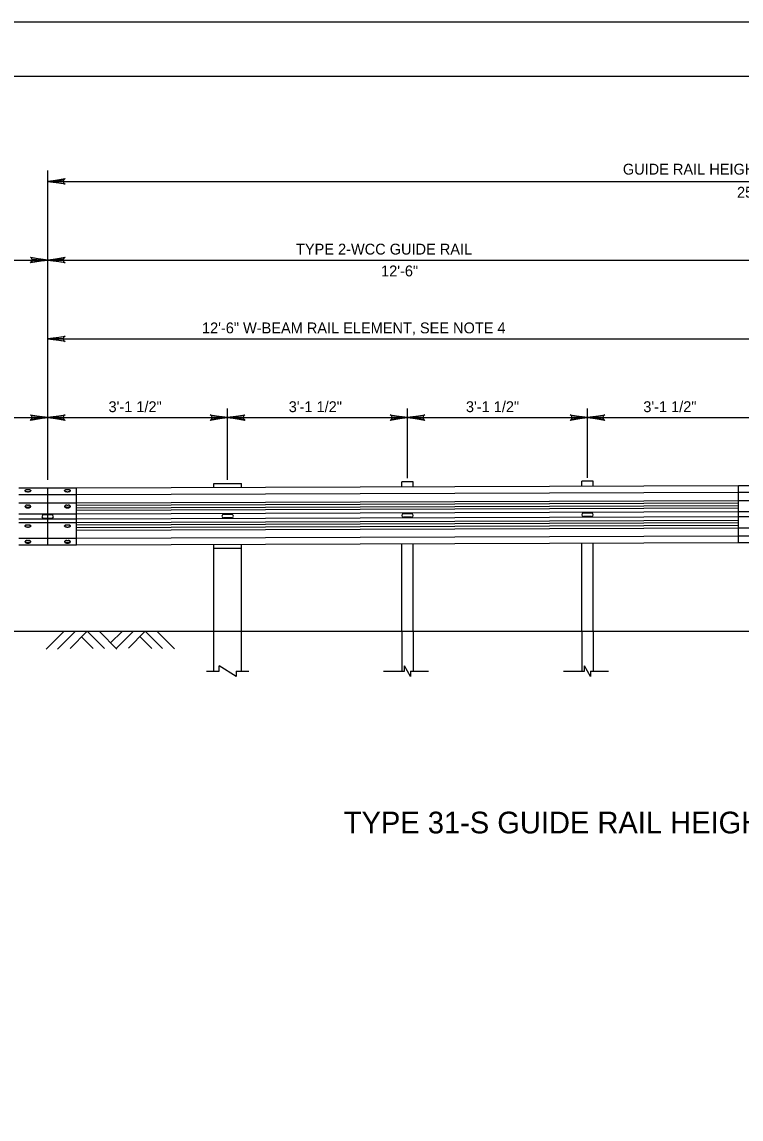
# Model space of a CAD drawing. Extents: x 637628 to 640188, y 298266 to 300751.
# Drawn here: x 639280.6 to 639479, y 299150.6 to 299453.6 of the extents above; entities that cross this region are included whole.
import ezdxf

# ---------------------------------------------------------------- set-up
doc = ezdxf.new("R2010")
doc.units = 0
for name, color, linetype in [('1', 7, 'Continuous'), ('2', 7, 'Continuous'), ('PLT-BNDY', 7, 'Continuous'), ('S-ABUT-CONC', 7, 'Continuous'), ('S-ANNO-CELL', 7, 'Continuous'), ('S-ANNO-T120-01', 7, 'Continuous')]:
    doc.layers.add(name, color=color, linetype=linetype)

msp = doc.modelspace()

# ---------------------------------------------------------------- linework, layer by layer
at = {"layer": '1'}
for p, q in [((639295.62, 299309.11), (639295.62, 299324.84)), ((639478.35, 299309.75), (639478.35, 299325.48))]:
    msp.add_line(p, q, dxfattribs=at)
msp.add_lwpolyline([(639945.52, 298874.58), (639945.52, 299438.55), (639159.55, 299438.55), (639159.55, 298874.58), (639945.52, 298874.58), (639945.52, 298900.93), (639745.53, 298900.93), (639745.53, 298965.61), (639945.52, 298965.61), (639945.52, 298994.57), (639745.53, 298994.57), (639745.53, 298874.58), (639824.33, 298874.58), (639824.33, 298900.93), (639824.33, 298874.58), (639901.33, 298874.58), (639901.33, 298900.93), (639901.33, 298888.62), (639945.52, 298888.62)], dxfattribs=at)
at = {"layer": '2'}
for p, q in [((639333.5, 299326.12), (639341.14, 299326.12)), ((639295.69, 299315.26), (639295.62, 299315.28)), ((639333.5, 299308.27), (639341.14, 299308.27)), ((639292.05, 299285.2), (639287.28, 299280.42)), ((639295.16, 299285.2), (639290.39, 299280.42)), ((639298.57, 299285.33), (639293.84, 299280.6)), ((639300.23, 299280.56), (639297.01, 299283.77)), ((639303.34, 299280.56), (639298.57, 299285.33)), ((639306.75, 299280.42), (639302.02, 299285.15)), ((639308.18, 299285.29), (639305.03, 299282.14)), ((639311.28, 299285.29), (639306.51, 299280.52)), ((639314.6, 299285.33), (639309.96, 299280.69)), ((639316.36, 299280.57), (639313.14, 299283.78)), ((639319.37, 299280.56), (639314.6, 299285.33)), ((639322.62, 299280.52), (639317.81, 299285.33)), ((639333.5, 299285.33), (639341.14, 299285.33))]:
    msp.add_line(p, q, dxfattribs=at)
for points in [[(639292.2, 299408.98), (639292.03, 299409.31), (639287.66, 299409.55), (639292.2, 299408.98), (639292.44, 299408.78), (639287.66, 299409.55), (639292.03, 299409.76), (639292.19, 299410.09), (639287.66, 299409.55), (639292.44, 299410.31), (639292.19, 299410.09)], [(639283.12, 299388.41), (639283.29, 299388.08), (639287.66, 299387.84), (639283.12, 299388.41), (639282.89, 299388.61), (639287.66, 299387.84), (639283.3, 299387.62), (639283.14, 299387.3), (639287.66, 299387.84), (639282.89, 299387.08), (639283.14, 299387.3)], [(639292.2, 299387.27), (639292.03, 299387.6), (639287.66, 299387.84), (639292.2, 299387.27), (639292.44, 299387.07), (639287.66, 299387.84), (639292.03, 299388.05), (639292.19, 299388.38), (639287.66, 299387.84), (639292.44, 299388.6), (639292.19, 299388.38)], [(639292.2, 299365.52), (639292.03, 299365.85), (639287.66, 299366.09), (639292.2, 299365.52), (639292.44, 299365.32), (639287.66, 299366.09), (639292.03, 299366.3), (639292.19, 299366.63), (639287.66, 299366.09), (639292.44, 299366.85), (639292.19, 299366.63)], [(639283.12, 299344.9), (639283.29, 299344.57), (639287.66, 299344.33), (639283.12, 299344.9), (639282.89, 299345.1), (639287.66, 299344.33), (639283.3, 299344.12), (639283.14, 299343.79), (639287.66, 299344.33), (639282.89, 299343.57), (639283.14, 299343.79)], [(639292.2, 299343.76), (639292.03, 299344.09), (639287.66, 299344.33), (639292.2, 299343.76), (639292.44, 299343.56), (639287.66, 299344.33), (639292.03, 299344.55), (639292.19, 299344.87), (639287.66, 299344.33), (639292.44, 299345.09), (639292.19, 299344.87)], [(639332.78, 299344.9), (639332.95, 299344.57), (639337.32, 299344.33), (639332.78, 299344.9), (639332.55, 299345.1), (639337.32, 299344.33), (639332.96, 299344.12), (639332.8, 299343.79), (639337.32, 299344.33), (639332.55, 299343.57), (639332.8, 299343.79)], [(639341.86, 299343.76), (639341.69, 299344.09), (639337.32, 299344.33), (639341.86, 299343.76), (639342.1, 299343.56), (639337.32, 299344.33), (639341.69, 299344.55), (639341.85, 299344.87), (639337.32, 299344.33), (639342.1, 299345.09), (639341.85, 299344.87)], [(639382.44, 299344.9), (639382.61, 299344.57), (639386.98, 299344.33), (639382.44, 299344.9), (639382.21, 299345.1), (639386.98, 299344.33), (639382.62, 299344.12), (639382.46, 299343.79), (639386.98, 299344.33), (639382.21, 299343.57), (639382.46, 299343.79)], [(639391.52, 299343.76), (639391.35, 299344.09), (639386.98, 299344.33), (639391.52, 299343.76), (639391.76, 299343.56), (639386.98, 299344.33), (639391.35, 299344.55), (639391.51, 299344.87), (639386.98, 299344.33), (639391.76, 299345.09), (639391.51, 299344.87)], [(639432.1, 299344.9), (639432.27, 299344.57), (639436.64, 299344.33), (639432.1, 299344.9), (639431.87, 299345.1), (639436.64, 299344.33), (639432.28, 299344.12), (639432.12, 299343.79), (639436.64, 299344.33), (639431.87, 299343.57), (639432.12, 299343.79)], [(639441.18, 299343.76), (639441.01, 299344.09), (639436.64, 299344.33), (639441.18, 299343.76), (639441.42, 299343.56), (639436.64, 299344.33), (639441.01, 299344.55), (639441.17, 299344.87), (639436.64, 299344.33), (639441.42, 299345.09), (639441.17, 299344.87)]]:
    msp.add_lwpolyline(points, dxfattribs=at)
at = {"layer": 'PLT-BNDY'}
msp.add_lwpolyline([(639119.52, 299453.58), (639960.52, 299453.58), (639960.52, 298859.58), (639119.52, 298859.58)], close=True, dxfattribs=at)
at = {"layer": 'S-ABUT-CONC'}
for p, q in [((639287.66, 299327.1), (639287.66, 299412.56)), ((639287.66, 299409.55), (639684.94, 299409.55)), ((639195.87, 299387.84), (639287.66, 299387.84)), ((639287.66, 299387.84), (639486.3, 299387.84)), ((639287.66, 299366.09), (639486.3, 299366.09)), ((639238, 299344.33), (639287.66, 299344.33)), ((639287.66, 299344.33), (639337.32, 299344.33)), ((639337.32, 299327.1), (639337.32, 299346.82)), ((639337.32, 299344.33), (639386.98, 299344.33)), ((639386.98, 299327.61), (639386.98, 299346.82)), ((639386.98, 299344.33), (639436.64, 299344.33)), ((639436.64, 299327.65), (639436.64, 299346.82)), ((639436.64, 299344.33), (639486.3, 299344.33))]:
    msp.add_line(p, q, dxfattribs=at)
at = {"layer": 'S-ANNO-CELL'}
for p, q in [((639333.5, 299324.98), (639333.5, 299326.12)), ((639341.14, 299325), (639341.14, 299326.12)), ((639388.57, 299326.56), (639385.39, 299326.56)), ((639385.39, 299325.16), (639385.39, 299326.56)), ((639388.57, 299325.17), (639388.57, 299326.56)), ((639438.23, 299326.74), (639435.05, 299326.74)), ((639435.05, 299325.33), (639435.05, 299326.74)), ((639438.23, 299325.34), (639438.23, 299326.74)), ((639295.62, 299324.84), (639279.71, 299324.84)), ((639295.62, 299322.99), (639279.71, 299322.99)), ((639282.05, 299324.5), (639282.37, 299324.5)), ((639282.05, 299324.39), (639282.05, 299324.5)), ((639282.37, 299324.39), (639282.05, 299324.39)), ((639282.05, 299323.79), (639282.37, 299323.79)), ((639282.37, 299324.39), (639282.37, 299324.5)), ((639287.66, 299309.24), (639287.66, 299324.84)), ((639292.96, 299324.5), (639293.28, 299324.5)), ((639292.96, 299324.39), (639292.96, 299324.5)), ((639293.28, 299324.39), (639292.96, 299324.39)), ((639292.96, 299323.79), (639293.28, 299323.79)), ((639293.28, 299324.39), (639293.28, 299324.5)), ((639478.35, 299325.48), (639295.62, 299324.84)), ((639478.35, 299323.63), (639295.62, 299322.99)), ((639494.26, 299325.48), (639478.35, 299325.48)), ((639494.26, 299323.63), (639478.35, 299323.63)), ((639295.62, 299320.73), (639279.71, 299320.73)), ((639282.05, 299320.15), (639282.37, 299320.15)), ((639292.96, 299320.15), (639293.28, 299320.15)), ((639478.35, 299321.37), (639295.62, 299320.73)), ((639478.35, 299320.68), (639295.62, 299320.05)), ((639478.35, 299320), (639295.62, 299319.36)), ((639494.26, 299321.37), (639478.35, 299321.37)), ((639295.62, 299317.68), (639279.71, 299317.68)), ((639282.05, 299319.54), (639282.05, 299319.43)), ((639282.37, 299319.54), (639282.05, 299319.54)), ((639282.05, 299319.43), (639282.37, 299319.43)), ((639282.37, 299319.54), (639282.37, 299319.43)), ((639287.66, 299317.45), (639286.55, 299317.45)), ((639288.78, 299317.45), (639287.66, 299317.45)), ((639292.96, 299319.54), (639292.96, 299319.43)), ((639293.28, 299319.54), (639292.96, 299319.54)), ((639292.96, 299319.43), (639293.28, 299319.43)), ((639293.28, 299319.54), (639293.28, 299319.43)), ((639478.35, 299319.31), (639295.62, 299318.67)), ((639478.35, 299318.31), (639295.62, 299317.68)), ((639478.35, 299316.91), (639295.62, 299316.27)), ((639337.32, 299317.6), (639336.21, 299317.6)), ((639337.32, 299317.6), (639336.21, 299317.6)), ((639338.44, 299317.6), (639337.32, 299317.6)), ((639338.44, 299317.6), (639337.32, 299317.6)), ((639386.98, 299317.77), (639385.87, 299317.77)), ((639386.98, 299317.77), (639385.87, 299317.77)), ((639386.98, 299317.77), (639385.87, 299317.77)), ((639386.98, 299317.77), (639385.87, 299317.77)), ((639388.1, 299317.77), (639386.98, 299317.77)), ((639388.1, 299317.77), (639386.98, 299317.77)), ((639388.1, 299317.77), (639386.98, 299317.77)), ((639388.1, 299317.77), (639386.98, 299317.77)), ((639436.64, 299317.94), (639435.53, 299317.94)), ((639436.64, 299317.94), (639435.53, 299317.94)), ((639436.64, 299316.99), (639435.53, 299316.99)), ((639436.64, 299316.99), (639435.53, 299316.99)), ((639437.76, 299317.94), (639436.64, 299317.94)), ((639437.76, 299317.94), (639436.64, 299317.94)), ((639437.76, 299316.99), (639436.64, 299316.99)), ((639437.76, 299316.99), (639436.64, 299316.99)), ((639494.26, 299318.31), (639478.35, 299318.31)), ((639494.26, 299316.91), (639478.35, 299316.91)), ((639295.62, 299316.27), (639279.71, 299316.27)), ((639295.62, 299315.28), (639279.71, 299315.28)), ((639282.05, 299314.75), (639282.37, 299314.75)), ((639282.05, 299314.64), (639282.05, 299314.75)), ((639282.37, 299314.64), (639282.05, 299314.64)), ((639282.05, 299314.04), (639282.37, 299314.04)), ((639282.37, 299314.64), (639282.37, 299314.75)), ((639287.66, 299316.5), (639286.55, 299316.5)), ((639288.78, 299316.5), (639287.66, 299316.5)), ((639292.96, 299314.75), (639293.28, 299314.75)), ((639292.96, 299314.64), (639292.96, 299314.75)), ((639293.28, 299314.64), (639292.96, 299314.64)), ((639292.96, 299314.04), (639293.28, 299314.04)), ((639293.28, 299314.64), (639293.28, 299314.75)), ((639478.35, 299315.92), (639295.62, 299315.28)), ((639478.35, 299315.23), (639295.62, 299314.6)), ((639478.35, 299314.5), (639295.62, 299313.86)), ((639478.35, 299313.82), (639295.62, 299313.18)), ((639337.32, 299316.64), (639336.21, 299316.64)), ((639337.32, 299316.64), (639336.21, 299316.64)), ((639338.44, 299316.64), (639337.32, 299316.64)), ((639338.44, 299316.64), (639337.32, 299316.64)), ((639386.98, 299316.82), (639385.87, 299316.82)), ((639386.98, 299316.82), (639385.87, 299316.82)), ((639388.1, 299316.82), (639386.98, 299316.82)), ((639388.1, 299316.82), (639386.98, 299316.82)), ((639494.26, 299313.82), (639478.35, 299313.82)), ((639295.62, 299310.96), (639279.71, 299310.96)), ((639478.35, 299311.6), (639295.62, 299310.96)), ((639494.26, 299311.6), (639478.35, 299311.6)), ((639295.62, 299309.11), (639279.71, 299309.11)), ((639282.05, 299310.4), (639282.37, 299310.4)), ((639282.05, 299309.79), (639282.05, 299309.68)), ((639282.37, 299309.79), (639282.05, 299309.79)), ((639282.05, 299309.68), (639282.37, 299309.68)), ((639282.37, 299309.79), (639282.37, 299309.68)), ((639292.96, 299310.4), (639293.28, 299310.4)), ((639292.96, 299309.79), (639292.96, 299309.68)), ((639293.28, 299309.79), (639292.96, 299309.79)), ((639292.96, 299309.68), (639293.28, 299309.68)), ((639293.28, 299309.79), (639293.28, 299309.68)), ((639478.35, 299309.75), (639295.62, 299309.11)), ((639333.5, 299285.33), (639333.5, 299309.25)), ((639341.14, 299285.33), (639341.14, 299309.27)), ((639385.39, 299285.33), (639385.39, 299309.43)), ((639388.57, 299285.33), (639388.57, 299309.44)), ((639435.05, 299285.33), (639435.05, 299309.6)), ((639438.23, 299285.33), (639438.23, 299309.61)), ((639494.26, 299309.75), (639478.35, 299309.75)), ((639238, 299285.33), (639581.11, 299285.33)), ((639333.5, 299274.31), (639333.5, 299285.33)), ((639341.14, 299274.31), (639341.14, 299285.33)), ((639385.39, 299285.33), (639385.39, 299274.31)), ((639388.57, 299285.33), (639388.57, 299274.31)), ((639435.05, 299285.33), (639435.05, 299274.31)), ((639438.23, 299285.33), (639438.23, 299274.31)), ((639335, 299274.31), (639335, 299275.81)), ((639339.64, 299272.81), (639335, 299275.81)), ((639386.16, 299274.31), (639386.16, 299275.81)), ((639387.8, 299272.81), (639386.16, 299275.81)), ((639435.82, 299274.31), (639435.82, 299275.81)), ((639437.46, 299272.81), (639435.82, 299275.81)), ((639331.5, 299274.31), (639335, 299274.31)), ((639339.64, 299274.31), (639339.64, 299272.81)), ((639339.64, 299274.31), (639343.14, 299274.31)), ((639380.39, 299274.31), (639384.62, 299274.31)), ((639381.16, 299274.31), (639386.16, 299274.31)), ((639387.8, 299274.31), (639387.8, 299272.81)), ((639387.8, 299274.31), (639392.8, 299274.31)), ((639430.05, 299274.31), (639434.28, 299274.31)), ((639430.82, 299274.31), (639435.82, 299274.31)), ((639437.46, 299274.31), (639437.46, 299272.81)), ((639437.46, 299274.31), (639442.46, 299274.31))]:
    msp.add_line(p, q, dxfattribs=at)
for points in [[(639282.05, 299323.79), (639281.94, 299323.79), (639281.83, 299323.81), (639281.73, 299323.83), (639281.64, 299323.87), (639281.56, 299323.91), (639281.5, 299323.97), (639281.45, 299324.02), (639281.42, 299324.08), (639281.41, 299324.14), (639281.42, 299324.21), (639281.45, 299324.27), (639281.5, 299324.32), (639281.56, 299324.37), (639281.64, 299324.42), (639281.73, 299324.45), (639281.83, 299324.48), (639281.94, 299324.49), (639282.05, 299324.5)], [(639282.05, 299324.39), (639281.94, 299324.38), (639281.83, 299324.37), (639281.73, 299324.34), (639281.64, 299324.31), (639281.56, 299324.26), (639281.5, 299324.21), (639281.45, 299324.15), (639281.42, 299324.09), (639281.42, 299324.09)], [(639282.37, 299324.5), (639282.48, 299324.49), (639282.58, 299324.48), (639282.68, 299324.45), (639282.77, 299324.42), (639282.85, 299324.37), (639282.92, 299324.32), (639282.96, 299324.27), (639282.99, 299324.21), (639283, 299324.14), (639282.99, 299324.08), (639282.96, 299324.02), (639282.92, 299323.97), (639282.85, 299323.91), (639282.77, 299323.87), (639282.68, 299323.83), (639282.58, 299323.81), (639282.48, 299323.79), (639282.37, 299323.79)], [(639282.99, 299324.09), (639282.99, 299324.09), (639282.96, 299324.15), (639282.92, 299324.21), (639282.85, 299324.26), (639282.77, 299324.31), (639282.68, 299324.34), (639282.58, 299324.37), (639282.48, 299324.38), (639282.37, 299324.39)], [(639292.96, 299323.79), (639292.85, 299323.79), (639292.74, 299323.81), (639292.64, 299323.83), (639292.55, 299323.87), (639292.47, 299323.91), (639292.41, 299323.97), (639292.36, 299324.02), (639292.33, 299324.08), (639292.32, 299324.14), (639292.33, 299324.21), (639292.36, 299324.27), (639292.41, 299324.32), (639292.47, 299324.37), (639292.55, 299324.42), (639292.64, 299324.45), (639292.74, 299324.48), (639292.85, 299324.49), (639292.96, 299324.5)], [(639292.96, 299324.39), (639292.85, 299324.38), (639292.74, 299324.37), (639292.64, 299324.34), (639292.55, 299324.31), (639292.47, 299324.26), (639292.41, 299324.21), (639292.36, 299324.15), (639292.33, 299324.09), (639292.33, 299324.09)], [(639293.28, 299324.5), (639293.39, 299324.49), (639293.5, 299324.48), (639293.6, 299324.45), (639293.69, 299324.42), (639293.77, 299324.37), (639293.83, 299324.32), (639293.88, 299324.27), (639293.91, 299324.21), (639293.92, 299324.14), (639293.91, 299324.08), (639293.88, 299324.02), (639293.83, 299323.97), (639293.77, 299323.91), (639293.69, 299323.87), (639293.6, 299323.83), (639293.5, 299323.81), (639293.39, 299323.79), (639293.28, 299323.79)], [(639293.91, 299324.09), (639293.91, 299324.09), (639293.88, 299324.15), (639293.83, 299324.21), (639293.77, 299324.26), (639293.69, 299324.31), (639293.6, 299324.34), (639293.5, 299324.37), (639293.39, 299324.38), (639293.28, 299324.39)], [(639282.05, 299320.15), (639281.94, 299320.14), (639281.83, 299320.12), (639281.73, 299320.1), (639281.64, 299320.06), (639281.56, 299320.02), (639281.5, 299319.97), (639281.45, 299319.91), (639281.42, 299319.85), (639281.41, 299319.79), (639281.42, 299319.73), (639281.45, 299319.67), (639281.5, 299319.61), (639281.56, 299319.56), (639281.64, 299319.52), (639281.73, 299319.48), (639281.83, 299319.45), (639281.94, 299319.44), (639282.05, 299319.43)], [(639282.37, 299319.43), (639282.48, 299319.44), (639282.58, 299319.45), (639282.68, 299319.48), (639282.77, 299319.52), (639282.85, 299319.56), (639282.92, 299319.61), (639282.96, 299319.67), (639282.99, 299319.73), (639283, 299319.79), (639282.99, 299319.85), (639282.96, 299319.91), (639282.92, 299319.97), (639282.85, 299320.02), (639282.77, 299320.06), (639282.68, 299320.1), (639282.58, 299320.12), (639282.48, 299320.14), (639282.37, 299320.15)], [(639292.96, 299320.15), (639292.85, 299320.14), (639292.74, 299320.12), (639292.64, 299320.1), (639292.55, 299320.06), (639292.47, 299320.02), (639292.41, 299319.97), (639292.36, 299319.91), (639292.33, 299319.85), (639292.32, 299319.79), (639292.33, 299319.73), (639292.36, 299319.67), (639292.41, 299319.61), (639292.47, 299319.56), (639292.55, 299319.52), (639292.64, 299319.48), (639292.74, 299319.45), (639292.85, 299319.44), (639292.96, 299319.43)], [(639293.28, 299319.43), (639293.39, 299319.44), (639293.5, 299319.45), (639293.6, 299319.48), (639293.69, 299319.52), (639293.77, 299319.56), (639293.83, 299319.61), (639293.88, 299319.67), (639293.91, 299319.73), (639293.92, 299319.79), (639293.91, 299319.85), (639293.88, 299319.91), (639293.83, 299319.97), (639293.77, 299320.02), (639293.69, 299320.06), (639293.6, 299320.1), (639293.5, 299320.12), (639293.39, 299320.14), (639293.28, 299320.15)], [(639282.05, 299319.54), (639281.94, 299319.55), (639281.83, 299319.57), (639281.73, 299319.59), (639281.64, 299319.63), (639281.56, 299319.67), (639281.5, 299319.72), (639281.45, 299319.78), (639281.42, 299319.84), (639281.42, 299319.84)], [(639282.99, 299319.84), (639282.99, 299319.84), (639282.96, 299319.78), (639282.92, 299319.72), (639282.85, 299319.67), (639282.77, 299319.63), (639282.68, 299319.59), (639282.58, 299319.57), (639282.48, 299319.55), (639282.37, 299319.54)], [(639292.96, 299319.54), (639292.85, 299319.55), (639292.74, 299319.57), (639292.64, 299319.59), (639292.55, 299319.63), (639292.47, 299319.67), (639292.41, 299319.72), (639292.36, 299319.78), (639292.33, 299319.84), (639292.33, 299319.84)], [(639293.91, 299319.84), (639293.91, 299319.84), (639293.88, 299319.78), (639293.83, 299319.72), (639293.77, 299319.67), (639293.69, 299319.63), (639293.6, 299319.59), (639293.5, 299319.57), (639293.39, 299319.55), (639293.28, 299319.54)], [(639282.05, 299314.04), (639281.94, 299314.04), (639281.83, 299314.06), (639281.73, 299314.08), (639281.64, 299314.12), (639281.56, 299314.16), (639281.5, 299314.22), (639281.45, 299314.27), (639281.42, 299314.33), (639281.41, 299314.39), (639281.42, 299314.46), (639281.45, 299314.52), (639281.5, 299314.57), (639281.56, 299314.62), (639281.64, 299314.67), (639281.73, 299314.7), (639281.83, 299314.73), (639281.94, 299314.74), (639282.05, 299314.75)], [(639282.05, 299314.64), (639281.94, 299314.63), (639281.83, 299314.62), (639281.73, 299314.59), (639281.64, 299314.56), (639281.56, 299314.51), (639281.5, 299314.46), (639281.45, 299314.4), (639281.42, 299314.34), (639281.42, 299314.34)], [(639282.37, 299314.75), (639282.48, 299314.74), (639282.58, 299314.73), (639282.68, 299314.7), (639282.77, 299314.67), (639282.85, 299314.62), (639282.92, 299314.57), (639282.96, 299314.52), (639282.99, 299314.46), (639283, 299314.39), (639282.99, 299314.33), (639282.96, 299314.27), (639282.92, 299314.22), (639282.85, 299314.16), (639282.77, 299314.12), (639282.68, 299314.08), (639282.58, 299314.06), (639282.48, 299314.04), (639282.37, 299314.04)], [(639282.99, 299314.34), (639282.99, 299314.34), (639282.96, 299314.4), (639282.92, 299314.46), (639282.85, 299314.51), (639282.77, 299314.56), (639282.68, 299314.59), (639282.58, 299314.62), (639282.48, 299314.63), (639282.37, 299314.64)], [(639292.96, 299314.04), (639292.85, 299314.04), (639292.74, 299314.06), (639292.64, 299314.08), (639292.55, 299314.12), (639292.47, 299314.16), (639292.41, 299314.22), (639292.36, 299314.27), (639292.33, 299314.33), (639292.32, 299314.39), (639292.33, 299314.46), (639292.36, 299314.52), (639292.41, 299314.57), (639292.47, 299314.62), (639292.55, 299314.67), (639292.64, 299314.7), (639292.74, 299314.73), (639292.85, 299314.74), (639292.96, 299314.75)], [(639292.96, 299314.64), (639292.85, 299314.63), (639292.74, 299314.62), (639292.64, 299314.59), (639292.55, 299314.56), (639292.47, 299314.51), (639292.41, 299314.46), (639292.36, 299314.4), (639292.33, 299314.34), (639292.33, 299314.34)], [(639293.28, 299314.75), (639293.39, 299314.74), (639293.5, 299314.73), (639293.6, 299314.7), (639293.69, 299314.67), (639293.77, 299314.62), (639293.83, 299314.57), (639293.88, 299314.52), (639293.91, 299314.46), (639293.92, 299314.39), (639293.91, 299314.33), (639293.88, 299314.27), (639293.83, 299314.22), (639293.77, 299314.16), (639293.69, 299314.12), (639293.6, 299314.08), (639293.5, 299314.06), (639293.39, 299314.04), (639293.28, 299314.04)], [(639293.91, 299314.34), (639293.91, 299314.34), (639293.88, 299314.4), (639293.83, 299314.46), (639293.77, 299314.51), (639293.69, 299314.56), (639293.6, 299314.59), (639293.5, 299314.62), (639293.39, 299314.63), (639293.28, 299314.64)], [(639282.05, 299310.4), (639281.94, 299310.39), (639281.83, 299310.37), (639281.73, 299310.35), (639281.64, 299310.31), (639281.56, 299310.27), (639281.5, 299310.22), (639281.45, 299310.16), (639281.42, 299310.1), (639281.41, 299310.04), (639281.42, 299309.98), (639281.45, 299309.92), (639281.5, 299309.86), (639281.56, 299309.81), (639281.64, 299309.77), (639281.73, 299309.73), (639281.83, 299309.7), (639281.94, 299309.69), (639282.05, 299309.68)], [(639282.05, 299309.79), (639281.94, 299309.8), (639281.83, 299309.82), (639281.73, 299309.84), (639281.64, 299309.88), (639281.56, 299309.92), (639281.5, 299309.97), (639281.45, 299310.03), (639281.42, 299310.09), (639281.42, 299310.09)], [(639282.37, 299309.68), (639282.48, 299309.69), (639282.58, 299309.7), (639282.68, 299309.73), (639282.77, 299309.77), (639282.85, 299309.81), (639282.92, 299309.86), (639282.96, 299309.92), (639282.99, 299309.98), (639283, 299310.04), (639282.99, 299310.1), (639282.96, 299310.16), (639282.92, 299310.22), (639282.85, 299310.27), (639282.77, 299310.31), (639282.68, 299310.35), (639282.58, 299310.37), (639282.48, 299310.39), (639282.37, 299310.4)], [(639282.99, 299310.09), (639282.99, 299310.09), (639282.96, 299310.03), (639282.92, 299309.97), (639282.85, 299309.92), (639282.77, 299309.88), (639282.68, 299309.84), (639282.58, 299309.82), (639282.48, 299309.8), (639282.37, 299309.79)], [(639292.96, 299310.4), (639292.85, 299310.39), (639292.74, 299310.37), (639292.64, 299310.35), (639292.55, 299310.31), (639292.47, 299310.27), (639292.41, 299310.22), (639292.36, 299310.16), (639292.33, 299310.1), (639292.32, 299310.04), (639292.33, 299309.98), (639292.36, 299309.92), (639292.41, 299309.86), (639292.47, 299309.81), (639292.55, 299309.77), (639292.64, 299309.73), (639292.74, 299309.7), (639292.85, 299309.69), (639292.96, 299309.68)], [(639292.96, 299309.79), (639292.85, 299309.8), (639292.74, 299309.82), (639292.64, 299309.84), (639292.55, 299309.88), (639292.47, 299309.92), (639292.41, 299309.97), (639292.36, 299310.03), (639292.33, 299310.09), (639292.33, 299310.09)], [(639293.28, 299309.68), (639293.39, 299309.69), (639293.5, 299309.7), (639293.6, 299309.73), (639293.69, 299309.77), (639293.77, 299309.81), (639293.83, 299309.86), (639293.88, 299309.92), (639293.91, 299309.98), (639293.92, 299310.04), (639293.91, 299310.1), (639293.88, 299310.16), (639293.83, 299310.22), (639293.77, 299310.27), (639293.69, 299310.31), (639293.6, 299310.35), (639293.5, 299310.37), (639293.39, 299310.39), (639293.28, 299310.4)], [(639293.91, 299310.09), (639293.91, 299310.09), (639293.88, 299310.03), (639293.83, 299309.97), (639293.77, 299309.92), (639293.69, 299309.88), (639293.6, 299309.84), (639293.5, 299309.82), (639293.39, 299309.8), (639293.28, 299309.79)]]:
    msp.add_lwpolyline(points, dxfattribs=at)
for centre, start, end in [((639286.55, 299316.97), 90, 270), ((639288.78, 299316.97), 270, 90), ((639336.21, 299317.12), 90, 270), ((639336.21, 299317.12), 90, 270), ((639338.44, 299317.12), 270, 90), ((639338.44, 299317.12), 270, 90), ((639385.87, 299317.29), 90, 270), ((639385.87, 299317.29), 90, 270), ((639388.1, 299317.29), 270, 90), ((639388.1, 299317.29), 270, 90), ((639435.53, 299317.47), 90, 270), ((639435.53, 299317.47), 90, 270), ((639437.76, 299317.47), 270, 90), ((639437.76, 299317.47), 270, 90)]:
    msp.add_arc(centre, 0.478, start, end, dxfattribs=at)

# ---------------------------------------------------------------- texts
at = {"layer": 'S-ABUT-CONC'}
for s, p in [('GUIDE RAIL HEIGHT TRANSITION', (639446.41, 299411.42)), ('25\'-0"', (639477.92, 299405.05)), ('TYPE 2-WCC GUIDE RAIL', (639356.21, 299389.34)), ('12\'-6"', (639379.68, 299383.32)), ('12\'-6" W-BEAM RAIL ELEMENT, SEE NOTE 4', (639330.25, 299367.59)), ('3\'-1 1/2"', (639304.45, 299345.83)), ('3\'-1 1/2"', (639354.19, 299345.83)), ('3\'-1 1/2"', (639403.1, 299345.83)), ('3\'-1 1/2"', (639452.05, 299345.83))]:
    msp.add_text(s, height=3, dxfattribs=at).set_placement(p)
at = {"layer": 'S-ANNO-T120-01'}
msp.add_text('TYPE 31-S GUIDE RAIL HEIGHT TRANSITION TO TYPE 2-W GUIDE RAIL', height=6, dxfattribs=at).set_placement((639369.39, 299229.51))

doc.saveas('drawing.dxf')
